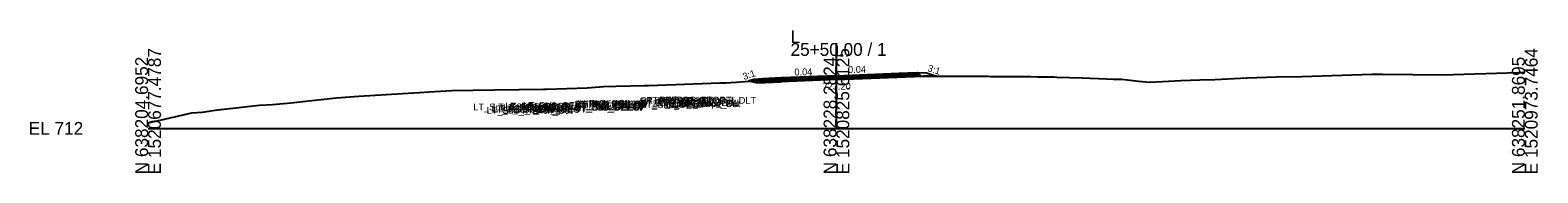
# Model space of a CAD drawing. Extents: x -26 to 3903, y -10 to 9531.
# Drawn here: x 974.3 to 1302.8, y 5490.3 to 5521.4 of the extents above; entities that cross this region are included whole.
import ezdxf

# ---------------------------------------------------------------- set-up
doc = ezdxf.new("R2010")
doc.units = 0
for name, color, linetype in [('Default', 7, 'Continuous'), ('Exist Cross Section Cell', 7, 'Continuous'), ('Exist XS Center Line Elevation Label', 7, 'Continuous'), ('Exist XS Ground Line', 7, 'Continuous'), ('Prop CMT Conc Surface', 7, 'Continuous'), ('Prop CMT Pvmt Course 1', 7, 'Continuous'), ('Prop CMT Pvmt Course 2', 7, 'Continuous'), ('Prop CMT Pvmt Course 3', 7, 'Continuous'), ('Prop CMT Pvmt Surface', 7, 'Continuous'), ('Prop CMT Pvmt Surface Shoulder', 7, 'Continuous'), ('Prop CMT Shld Paved Course 1', 7, 'Continuous'), ('Prop CMT Shld Paved Course 2', 7, 'Continuous'), ('Prop CMT Shld Paved Course 3', 7, 'Continuous'), ('Prop CMT Slope Grass', 7, 'Continuous'), ('Prop CMT Subgrade Earthwork', 7, 'Continuous'), ('Prop XS Earthwork Shape', 7, 'Continuous'), ('Prop XS SE Text', 7, 'Continuous'), ('Prop XS Side Slope Text', 7, 'Continuous')]:
    doc.layers.add(name, color=color, linetype=linetype)

msp = doc.modelspace()

# ---------------------------------------------------------------- linework, layer by layer
at = {"layer": 'Exist Cross Section Cell'}
for p, q in [((1150, 5500), (1150, 5518.6)), ((1000, 5500), (1150, 5500)), ((1150, 5500), (1300, 5500))]:
    msp.add_line(p, q, dxfattribs=at)
at = {"layer": 'Exist XS Ground Line'}
msp.add_lwpolyline([(1000, 5501.2), (1001.96, 5501.65), (1009.53, 5503.35), (1011.82, 5503.51), (1015.16, 5504.02), (1015.25, 5504.07), (1015.86, 5504.11), (1024.26, 5505.03), (1027.08, 5505.23), (1031.11, 5505.58), (1040.31, 5506.59), (1040.97, 5506.65), (1045.9, 5507), (1055.43, 5507.57), (1059.13, 5507.8), (1061.29, 5507.95), (1066.2, 5508.27), (1075.51, 5508.39), (1075.53, 5508.39), (1075.54, 5508.4), (1086.18, 5508.52), (1086.8, 5508.54), (1095.71, 5508.83), (1099.25, 5509.16), (1102.01, 5509.18), (1108.12, 5509.35), (1109.05, 5509.35), (1113.03, 5509.51), (1116.89, 5509.61), (1124.61, 5509.89), (1125.89, 5509.94), (1126.96, 5510), (1128.2, 5510.09), (1137.64, 5510.77), (1138.36, 5510.84), (1138.48, 5510.84), (1138.67, 5510.86), (1138.79, 5510.87), (1139.21, 5510.89), (1140.69, 5510.93), (1142.15, 5510.96), (1143.23, 5510.99), (1144.73, 5511.03), (1145.76, 5511.06), (1146.5, 5511.08), (1148.29, 5511.14), (1148.69, 5511.15), (1150, 5511.2), (1150.81, 5511.23), (1150.86, 5511.23), (1151.21, 5511.24), (1153.04, 5511.26), (1153.32, 5511.26), (1153.56, 5511.27), (1154.71, 5511.3), (1155.39, 5511.3), (1155.85, 5511.3), (1156.73, 5511.31), (1158.38, 5511.33), (1159.75, 5511.33), (1160.91, 5511.34), (1161.67, 5511.35), (1163.15, 5511.36), (1163.36, 5511.37), (1163.77, 5511.36), (1164.42, 5511.37), (1166.17, 5511.38), (1166.39, 5511.38), (1167.44, 5511.39), (1168.52, 5511.4), (1170.52, 5511.39), (1171.05, 5511.38), (1172.7, 5511.39), (1173.57, 5511.39), (1174.88, 5511.39), (1176.11, 5511.4), (1176.91, 5511.4), (1178.55, 5511.39), (1179.61, 5511.38), (1179.67, 5511.38), (1179.77, 5511.38), (1181.17, 5511.36), (1181.42, 5511.36), (1183.07, 5511.35), (1183.51, 5511.34), (1183.7, 5511.34), (1185.81, 5511.32), (1186.24, 5511.32), (1187.98, 5511.3), (1188.77, 5511.3), (1190.18, 5511.29), (1191.31, 5511.27), (1192.35, 5511.27), (1193.83, 5511.25), (1194.16, 5511.24), (1196.07, 5511.24), (1197.4, 5511.22), (1198.06, 5511.19), (1203.52, 5510.98), (1208.85, 5510.8), (1210.37, 5510.75), (1212.19, 5510.7), (1215.81, 5510.32), (1218.22, 5510.1), (1219.67, 5510.15), (1225.06, 5510.42), (1229.17, 5510.56), (1232.45, 5510.64), (1239.46, 5511.01), (1245.87, 5511.2), (1251.44, 5511.29), (1266.68, 5511.8), (1269.08, 5511.84), (1282.14, 5511.7), (1298.47, 5512.18), (1300, 5512.19)], dxfattribs=at)
at = {"layer": 'Prop CMT Pvmt Course 1'}
for points in [[(1149.97, 5511.46), (1137.97, 5510.98)], [(1137.97, 5510.73), (1149.97, 5511.21)], [(1137.97, 5510.98), (1137.97, 5510.73)], [(1149.97, 5511.46), (1163.6, 5512.01)], [(1163.6, 5511.76), (1149.97, 5511.21)], [(1149.97, 5511.21), (1149.97, 5511.46)], [(1149.97, 5511.21), (1149.97, 5511.46)], [(1163.6, 5512.01), (1163.6, 5511.76)]]:
    msp.add_lwpolyline(points, dxfattribs=at)
msp.add_lwpolyline([(1149.97, 5511.21), (1149.97, 5511.33), (1149.97, 5511.33), (1149.97, 5511.21)], close=True, dxfattribs=at)
msp.add_lwpolyline([(1149.97, 5511.21), (1149.97, 5511.33), (1149.97, 5511.33), (1149.97, 5511.21)], close=True, dxfattribs=at)
at = {"layer": 'Prop CMT Pvmt Course 2'}
for points in [[(1149.97, 5511.21), (1137.97, 5510.73)], [(1137.97, 5510.73), (1137.97, 5510.4)], [(1149.97, 5511.21), (1163.6, 5511.76)], [(1149.97, 5510.88), (1149.97, 5511.21)], [(1149.97, 5510.88), (1149.97, 5511.21)]]:
    msp.add_lwpolyline(points, dxfattribs=at)
at = {"layer": 'Prop CMT Pvmt Course 3'}
for points in [[(1137.97, 5510.4), (1137.97, 5510.15)], [(1149.97, 5510.63), (1149.97, 5510.88)], [(1149.97, 5510.63), (1149.97, 5510.88)]]:
    msp.add_lwpolyline(points, dxfattribs=at)
at = {"layer": 'Prop CMT Pvmt Surface'}
for points in [[(1149.97, 5511.46), (1137.97, 5510.98)], [(1149.97, 5511.46), (1163.6, 5512.01)]]:
    msp.add_lwpolyline(points, dxfattribs=at)
at = {"layer": 'Prop CMT Pvmt Surface Shoulder'}
for points in [[(1137.97, 5510.98), (1133.97, 5510.82)], [(1163.6, 5512.01), (1167.6, 5512.17)]]:
    msp.add_lwpolyline(points, dxfattribs=at)
at = {"layer": 'Prop CMT Shld Paved Course 1'}
for points in [[(1137.97, 5510.98), (1133.97, 5510.82), (1133.71, 5510.56)], [(1133.71, 5510.56), (1137.97, 5510.73)], [(1137.97, 5510.73), (1137.97, 5510.98)], [(1167.84, 5511.92), (1150, 5511.21)], [(1163.6, 5512.01), (1167.6, 5512.17), (1167.84, 5511.92)], [(1163.6, 5511.76), (1163.6, 5512.01)]]:
    msp.add_lwpolyline(points, dxfattribs=at)
at = {"layer": 'Prop CMT Shld Paved Course 2'}
for points in [[(1150, 5511.21), (1133.71, 5510.56), (1133.37, 5510.21)], [(1133.37, 5510.21), (1137.97, 5510.4)], [(1137.97, 5510.4), (1137.97, 5510.73)], [(1150, 5511.21), (1167.84, 5511.92), (1168.16, 5511.6)], [(1168.16, 5511.6), (1163.6, 5511.42)]]:
    msp.add_lwpolyline(points, dxfattribs=at)
at = {"layer": 'Prop CMT Shld Paved Course 3'}
for points in [[(1132.61, 5509.93), (1137.97, 5510.15)], [(1150, 5510.88), (1133.37, 5510.21), (1133.1, 5509.95)], [(1137.97, 5510.15), (1137.97, 5510.4)], [(1150, 5510.88), (1168.16, 5511.6), (1168.4, 5511.36)], [(1168.9, 5511.38), (1163.6, 5511.17)]]:
    msp.add_lwpolyline(points, dxfattribs=at)
at = {"layer": 'Prop CMT Slope Grass'}
for points in [[(1133.97, 5510.82), (1131.97, 5510.66), (1130.83, 5510.28)], [(1167.6, 5512.17), (1169.6, 5512.13), (1171.81, 5511.39)]]:
    msp.add_lwpolyline(points, dxfattribs=at)
at = {"layer": 'Prop CMT Subgrade Earthwork'}
for points in [[(1132.61, 5509.93), (1130.83, 5510.28)], [(1150, 5510.63), (1132.61, 5509.93)], [(1150, 5510.63), (1168.9, 5511.38)], [(1168.9, 5511.38), (1171.81, 5511.39)]]:
    msp.add_lwpolyline(points, dxfattribs=at)
at = {"layer": 'Prop XS Earthwork Shape'}
for points in [[(1150, 5511.2), (1150.81, 5511.23), (1151.21, 5511.24), (1153.04, 5511.26), (1153.32, 5511.26), (1153.56, 5511.27), (1154.71, 5511.3), (1155.39, 5511.3), (1155.85, 5511.3), (1156.73, 5511.31), (1158.38, 5511.33), (1159.75, 5511.33), (1160.91, 5511.34), (1161.67, 5511.35), (1163.15, 5511.36), (1163.36, 5511.37), (1163.77, 5511.36), (1164.42, 5511.37), (1166.17, 5511.38), (1166.39, 5511.38), (1167.44, 5511.39), (1168.52, 5511.4), (1170.52, 5511.39), (1168.9, 5511.38), (1150, 5510.63), (1132.61, 5509.93), (1130.83, 5510.28), (1137.64, 5510.77), (1138.36, 5510.84), (1138.48, 5510.84), (1138.67, 5510.86), (1138.79, 5510.87), (1139.21, 5510.89), (1140.69, 5510.93), (1142.15, 5510.96), (1143.23, 5510.99), (1144.73, 5511.03), (1145.76, 5511.06), (1146.5, 5511.08), (1148.29, 5511.14), (1148.69, 5511.15)], [(1163.15, 5511.36), (1163.36, 5511.37), (1163.77, 5511.36), (1164.42, 5511.37), (1166.17, 5511.38), (1166.39, 5511.38), (1167.44, 5511.39), (1168.52, 5511.4), (1170.52, 5511.39), (1168.9, 5511.38), (1150, 5510.63), (1132.61, 5509.93), (1130.83, 5510.28), (1137.64, 5510.77), (1138.36, 5510.84), (1138.48, 5510.84), (1138.67, 5510.86), (1138.79, 5510.87), (1139.21, 5510.89), (1140.69, 5510.93), (1142.15, 5510.96), (1143.23, 5510.99), (1144.73, 5511.03), (1145.76, 5511.06), (1146.5, 5511.08), (1148.29, 5511.14), (1148.69, 5511.15), (1150, 5511.2), (1150.81, 5511.23), (1151.21, 5511.24), (1153.04, 5511.26), (1153.32, 5511.26), (1153.56, 5511.27), (1154.71, 5511.3), (1155.39, 5511.3), (1155.85, 5511.3), (1156.73, 5511.31), (1158.38, 5511.33), (1159.75, 5511.33), (1160.91, 5511.34), (1161.67, 5511.35)], [(1170.52, 5511.39), (1171.81, 5511.39), (1171.05, 5511.38)], [(1170.52, 5511.39), (1171.05, 5511.38), (1171.81, 5511.39)]]:
    msp.add_lwpolyline(points, close=True, dxfattribs=at)

# ---------------------------------------------------------------- texts
at = {"layer": 'Default'}
msp.add_text('-', height=0.0001, dxfattribs=at).set_placement((1000, 5500))
at = {"layer": 'Exist Cross Section Cell'}
for s, p in [('L', (1140, 5518.6)), ('25+50.00 / 1', (1140, 5515.8)), ('EL 712', (974, 5498.6))]:
    msp.add_text(s, height=2.8, dxfattribs=at).set_placement(p)
for s, p in [('E 1520677.4787', (1002.8, 5490)), ('E 1520825.6125', (1152.8, 5490)), ('E 1520973.7464', (1302.8, 5490)), ('N 638204.6952', (1000, 5490)), ('N 638228.2824', (1150, 5490)), ('N 638251.8695', (1300, 5490))]:
    msp.add_text(s, height=2.8, rotation=90, dxfattribs=at).set_placement(p)
at = {"layer": 'Exist XS Center Line Elevation Label'}
msp.add_text('723.20', height=1.5, rotation=0.8401, dxfattribs=at).set_placement((1146.99, 5508.38))
at = {"layer": 'Prop CMT Conc Surface'}
for s, p in [('PV1_PGL', (1096.17, 5504.71)), ('RT_PV2_OEOT', (1107.13, 5505.01)), ('RT_PV1_OEOT', (1107.31, 5505.26)), ('RT_Sub_Trench_Out_DLT', (1108.53, 5505.37)), ('RT_Sub_Trench_Out', (1109.98, 5504.63)), ('RT_PS3_Shelf_Out', (1110.56, 5504.87)), ('RT_PS1_OEOP', (1111.37, 5505.42)), ('RT_PS2_OEOP', (1111.43, 5505.17)), ('RT_PS3_OEOP', (1111.75, 5504.85)), ('RT_GS_OS_CTL', (1112.71, 5505.38)), ('RT_Slope_Fill', (1116.04, 5504.65)), ('LT_Sub_Trench_Out_DLT', (1070.86, 5503.9)), ('LT_Sub_Trench_Out', (1073.77, 5503.18)), ('LT_PS3_Shelf_Out', (1074.85, 5503.44)), ('LT_GS_OS_CTL', (1075.17, 5503.91)), ('LT_Slope_Fill', (1075.18, 5503.53)), ('LT_PS3_OEOP', (1077.05, 5503.46)), ('LT_PS2_OEOP', (1077.39, 5503.81)), ('LT_PS1_OEOP', (1077.83, 5504.07)), ('LT_PV2_OEOT', (1081.59, 5503.98)), ('LT_PV3_OEOT', (1081.59, 5503.65)), ('LT_Sub_OEOT', (1081.63, 5503.4)), ('LT_PV1_OEOT', (1081.77, 5504.23)), ('RT_PV2_OEEOP', (1092.97, 5504.46)), ('RT_PV3_OEEOP', (1092.97, 5504.13)), ('RT_Sub_OEEOP', (1093.01, 5503.88)), ('LT_PV2_OEEOP', (1093.06, 5504.46)), ('LT_PV3_OEEOP', (1093.06, 5504.13)), ('LT_Sub_OEEOP', (1093.09, 5503.88)), ('RT_PV1_OEEOP', (1093.15, 5504.58)), ('LT_PV1_OEEOP', (1093.24, 5504.58)), ('RT_PV2_IEEOP', (1093.54, 5504.46)), ('LT_PV2_IEEOP', (1093.63, 5504.46)), ('RT_PV1_IEEOP', (1093.72, 5504.58)), ('LT_PV1_IEEOP', (1093.81, 5504.58)), ('PV2_PGL', (1095.99, 5504.46)), ('RT_PV3_OEOT', (1107.13, 5504.67)), ('RT_Sub_OEOT', (1107.17, 5504.42))]:
    msp.add_text(s, height=1.5, dxfattribs=at).set_placement(p)
at = {"layer": 'Prop XS SE Text'}
for p in [(1140.86, 5511.52), (1152.55, 5512.06)]:
    msp.add_text('0.04', height=1.5, rotation=1.1458, dxfattribs=at).set_placement(p)
at = {"layer": 'Prop XS Side Slope Text'}
for rotation, p in [(341.5668, (1169.73, 5512.53)), (18.4332, (1129.85, 5510.52))]:
    msp.add_text('3:1', height=1.5, rotation=rotation, dxfattribs=at).set_placement(p)

doc.saveas('drawing.dxf')
